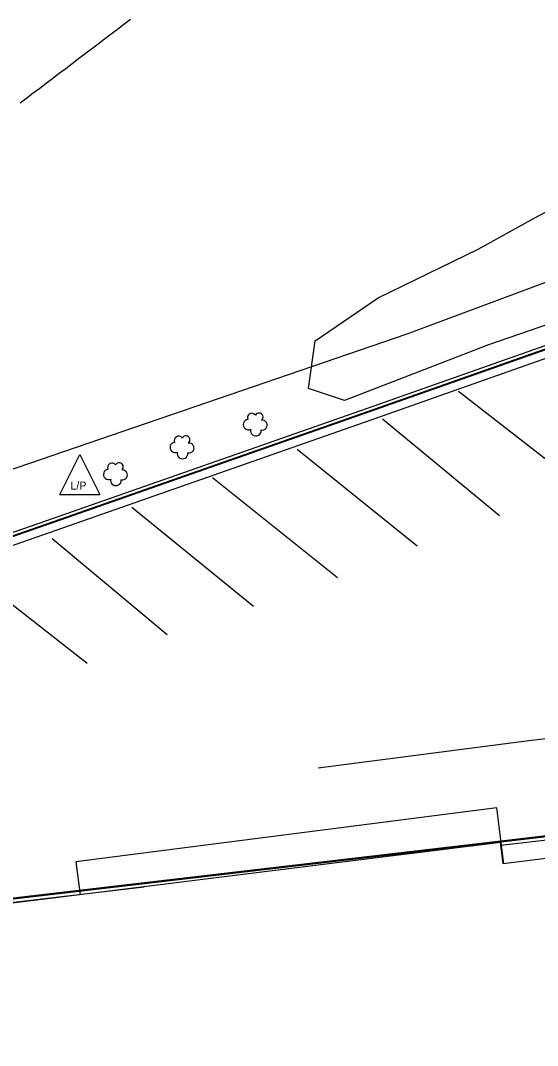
# Model space of a CAD drawing. Extents: x 1901471 to 1963503, y 756461 to 799997.
# Drawn here: x 1929745 to 1929808.6, y 772576.3 to 772702.4 of the extents above; entities that cross this region are included whole.
import ezdxf

# ---------------------------------------------------------------- set-up
doc = ezdxf.new("R2010")
doc.units = 0
for name, color, linetype in [('RD_EX_Bldg', 7, 'Continuous'), ('RD_EX_BldgApp', 7, 'Continuous'), ('RD_EX_Conc', 7, 'Continuous'), ('RD_EX_Fence_Other', 7, 'Continuous'), ('RD_EX_H2O', 7, 'Continuous'), ('RD_EX_Road', 7, 'Continuous'), ('RD_EX_UT', 7, 'Continuous'), ('RD_EX_VEG', 7, 'Continuous')]:
    doc.layers.add(name, color=color, linetype=linetype)

# ---------------------------------------------------------------- blocks, each defined once
blk = doc.blocks.new('SB2')
at = {"layer": 'RD_EX_VEG'}
for centre, radius, start, end in [((-0.72, 1.55), 1.08, 34.9763, 204.756), ((1.05, 1.7), 0.995, 308.7626, 152.0467), ((-1.56, -0.16), 1.26, 96.4518, 294.734), ((1.84, -0.28), 1.22, 256.5667, 98.1046), ((0.25, -1.6), 1.32, 166.8827, 5.7589)]:
    blk.add_arc(centre, radius, start, end, dxfattribs=at)
blk = doc.blocks.new('LP')
at = {"layer": 'RD_EX_UT'}
for p, q in [((-5, -3.72), (0, 6.28)), ((0, 6.28), (5, -3.72)), ((-5, -3.72), (5, -3.72))]:
    blk.add_line(p, q, dxfattribs=at)
blk.add_text('L/P', height=2, dxfattribs=at).set_placement((-2.4, -2.44))

msp = doc.modelspace()

# ---------------------------------------------------------------- linework, layer by layer
at = {"layer": 'RD_EX_Bldg'}
msp.add_lwpolyline([(1929729.45, 772547.77), (1929839.97, 772561.48), (1929835.82, 772594.93), (1929825.31, 772593.62), (1929824.38, 772601.12), (1929804.33, 772598.63), (1929804, 772601.24), (1929742.69, 772593.63), (1929743.42, 772587.74), (1929711.76, 772583.81), (1929683.02, 772545.83), (1929684.08, 772537.3), (1929730.04, 772543.01)], close=True, dxfattribs=at)
at = {"layer": 'RD_EX_BldgApp'}
for points in [[(1929803.55, 772605.53), (1929751.78, 772598.87), (1929752.3, 772594.82)], [(1929804.43, 772598.65), (1929803.55, 772605.53)]]:
    msp.add_lwpolyline(points, dxfattribs=at)
at = {"layer": 'RD_EX_Conc'}
for points in [[(1929818.65, 772665.59), (1929787.63, 772654.66), (1929748.03, 772640.8), (1929705.53, 772625.99), (1929700.95, 772619.84), (1929709.34, 772614.36), (1929711.28, 772612.96), (1929711.56, 772612.25), (1929711.57, 772611.67), (1929711.15, 772611.01), (1929710.56, 772610.45), (1929709.71, 772610.24), (1929708.74, 772610.02), (1929689.83, 772613.26), (1929674.02, 772596.83), (1929647.69, 772569.61)], [(1929818.56, 772665.14), (1929787.76, 772654.28), (1929748.16, 772640.43), (1929705.78, 772625.66), (1929701.53, 772619.94), (1929709.57, 772614.69), (1929711.61, 772613.22), (1929711.96, 772612.32), (1929711.97, 772611.56), (1929711.46, 772610.75), (1929710.77, 772610.09), (1929709.81, 772609.85), (1929708.75, 772609.61), (1929689.97, 772612.83), (1929674.31, 772596.55), (1929648.04, 772569.39)], [(1929818.54, 772665.03), (1929787.79, 772654.19), (1929748.2, 772640.33), (1929705.84, 772625.57), (1929701.67, 772619.96), (1929709.62, 772614.77), (1929711.7, 772613.28), (1929712.06, 772612.34), (1929712.07, 772611.53), (1929711.54, 772610.69), (1929710.82, 772610), (1929709.83, 772609.75), (1929708.75, 772609.51), (1929690.01, 772612.73), (1929674.38, 772596.48), (1929648.13, 772569.34)], [(1929712.67, 772583.93), (1929715.18, 772587.07), (1929717.3, 772588.53), (1929719.79, 772590.23), (1929721.87, 772591.22), (1929723.4, 772591.65), (1929733.88, 772593.13), (1929811.1, 772602.14)], [(1929804.04, 772600.92), (1929811.15, 772601.75)], [(1929713.24, 772584), (1929715.46, 772586.78), (1929717.53, 772588.2), (1929719.99, 772589.88), (1929722.01, 772590.85), (1929723.48, 772591.25), (1929733.93, 772592.74), (1929760.2, 772595.8)]]:
    msp.add_lwpolyline(points, dxfattribs=at)
at = {"layer": 'RD_EX_Fence_Other'}
msp.add_lwpolyline([(1930230.69, 773075.39), (1930202.12, 773046.67), (1930160.84, 773005.63), (1930128.22, 772972.13), (1930093.2, 772937.02), (1930073.43, 772918.59), (1930046.34, 772888.73), (1930044.81, 772868.05), (1930041.7, 772840.72), (1929994.8, 772796.32), (1929941.04, 772746.6), (1929894.33, 772713.92), (1929883.55, 772706.62), (1929817.78, 772673.24), (1929792.5, 772663.78), (1929741.61, 772646.35), (1929701.32, 772635.07), (1929691.74, 772624.27), (1929671.21, 772603.84), (1929649.68, 772579.5)], dxfattribs=at)
at = {"layer": 'RD_EX_H2O'}
msp.add_lwpolyline([(1929744.95, 772692.26), (1929745.74, 772692.87), (1929746.54, 772693.47), (1929747.34, 772694.07), (1929748.13, 772694.68), (1929748.93, 772695.28), (1929749.73, 772695.89), (1929750.53, 772696.49), (1929751.32, 772697.09), (1929752.12, 772697.7), (1929752.92, 772698.3), (1929753.71, 772698.9), (1929754.51, 772699.51), (1929755.31, 772700.11), (1929756.11, 772700.72), (1929756.11, 772700.72), (1929756.9, 772701.32), (1929757.7, 772701.92), (1929758.5, 772702.53)], dxfattribs=at)
at = {"layer": 'RD_EX_Road'}
for points in [[(1929649, 772568.8), (1929675.1, 772595.79), (1929690.36, 772611.65), (1929708.78, 772608.49), (1929710.06, 772608.78), (1929711.32, 772609.1), (1929712.32, 772610.05), (1929713.07, 772611.24), (1929713.06, 772612.53), (1929712.52, 772613.92), (1929710.19, 772615.6), (1929703.11, 772620.22), (1929706.46, 772624.73), (1929748.53, 772639.39), (1929788.12, 772653.24), (1929818.34, 772663.9)], [(1929814.69, 772644.42), (1929798.86, 772656.75)], [(1929803.89, 772641.44), (1929789.5, 772653.32)], [(1929793.77, 772637.7), (1929779.02, 772649.62)], [(1929783.96, 772633.81), (1929768.61, 772646.13)], [(1929773.62, 772630.3), (1929758.68, 772642.48)], [(1929763.03, 772626.82), (1929748.85, 772638.63)], [(1929753.16, 772623.27), (1929737.81, 772635.29)], [(1929826.3, 772615.98), (1929807.52, 772613.77), (1929781.57, 772610.39)], [(1929811.08, 772602.24), (1929733.86, 772593.23), (1929733.72, 772594.22), (1929723.18, 772592.72), (1929721.48, 772592.26), (1929719.24, 772591.18), (1929716.68, 772589.44), (1929714.42, 772587.89), (1929682.06, 772547.38)]]:
    msp.add_lwpolyline(points, dxfattribs=at)
at = {"layer": 'RD_EX_VEG'}
msp.add_lwpolyline([(1929910.25, 772710.26), (1929902.87, 772701.22), (1929874.65, 772685.01), (1929835, 772672.17), (1929822.55, 772669.37), (1929802.55, 772662.46), (1929784.81, 772655.65), (1929780.4, 772657.12), (1929781.22, 772662.97), (1929788.98, 772668.27), (1929801.27, 772674.26), (1929808.62, 772678.32), (1929816.82, 772682.53), (1929817.5, 772682.94), (1929832.41, 772696.28), (1929853.7, 772705.81)], dxfattribs=at)

# ---------------------------------------------------------------- block references
at = {"layer": 'RD_EX_UT', "xscale": 0.4921259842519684, "yscale": 0.4921259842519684}
msp.add_blockref('LP', (1929752.29, 772645.88), dxfattribs=at)
at = {"layer": 'RD_EX_VEG', "xscale": 0.5019685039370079, "yscale": 0.5019685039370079}
for p in [(1929773.79, 772652.74), (1929764.78, 772649.93), (1929756.59, 772646.62)]:
    msp.add_blockref('SB2', p, dxfattribs=at)

doc.saveas('drawing.dxf')
